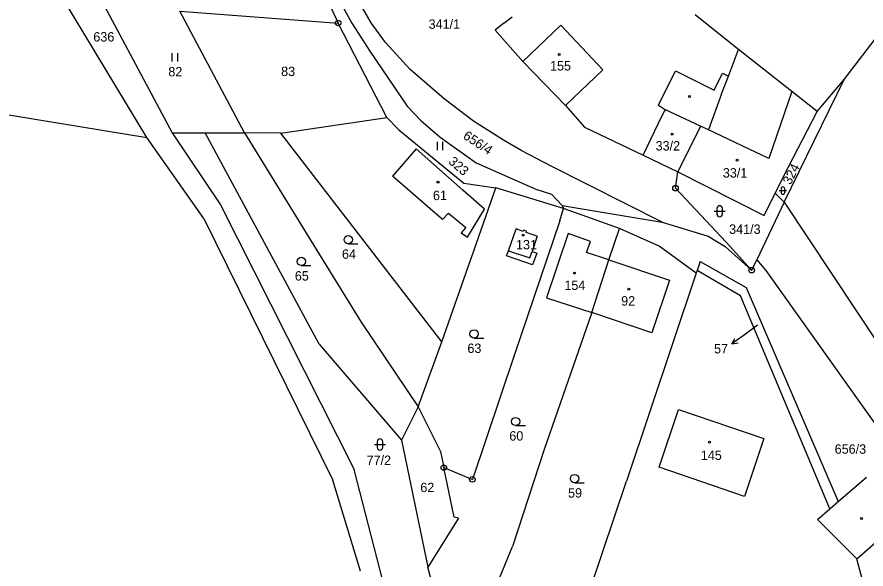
# Model space of a CAD drawing. Extents: x -654459 to -653618, y -1151040 to -1150446.
# Drawn here: x -654178.6 to -654025.1, y -1150786 to -1150686.2 of the extents above; entities that cross this region are included whole.
import ezdxf

# ---------------------------------------------------------------- set-up
doc = ezdxf.new("R2010")
doc.units = 0
for name, color, linetype in [('Vrstva 1', 7, 'Continuous'), ('Vrstva 13', 7, 'Continuous'), ('Vrstva 2', 7, 'Continuous'), ('Vrstva 3', 7, 'Continuous'), ('Vrstva 4', 7, 'Continuous'), ('Vrstva 5', 7, 'Continuous'), ('Vrstva 7', 7, 'Continuous'), ('Vrstva 8', 7, 'Continuous')]:
    doc.layers.add(name, color=color, linetype=linetype)

msp = doc.modelspace()

# ---------------------------------------------------------------- linework, layer by layer
at = {"layer": 'Vrstva 1'}
for points in [[(-654131.26, -1150664.02), (-654120.48, -1150687.29)], [(-654121.84, -1150680.33), (-654118.03, -1150687.34)], [(-654155.05, -1150708), (-654170.17, -1150682.99)], [(-654114.5, -1150687.25), (-654117, -1150682.92)], [(-654162.76, -1150684.14), (-654150.52, -1150707.15)], [(-654149.12, -1150685.15), (-654120.48, -1150687.29)], [(-654137.41, -1150707.13), (-654149.12, -1150685.15)], [(-654090.53, -1150687.32), (-654089.06, -1150686.16)], [(-654048.66, -1150691.65), (-654055.93, -1150685.84)], [(-654111.68, -1150704.37), (-654120.48, -1150687.29)], [(-654118.03, -1150687.34), (-654114.77, -1150692.4)], [(-654111.96, -1150690.82), (-654114.5, -1150687.25)], [(-654090.53, -1150687.32), (-654092.08, -1150688.61)], [(-654087.09, -1150694.22), (-654092.08, -1150688.61)], [(-654080.26, -1150687.68), (-654087.09, -1150694.22)], [(-654072.67, -1150695.73), (-654080.26, -1150687.68)], [(-654028.99, -1150697.51), (-654022.86, -1150689.48)], [(-654107.45, -1150695.69), (-654111.96, -1150690.82)], [(-654048.1, -1150692.09), (-654048.66, -1150691.65)], [(-654114.77, -1150692.4), (-654108.01, -1150702.3)], [(-654049.94, -1150696.9), (-654048.1, -1150692.09)], [(-654038.48, -1150699.66), (-654048.1, -1150692.09)], [(-654079.42, -1150702.23), (-654087.09, -1150694.22)], [(-654231.14, -1150695.5), (-654155.05, -1150708)], [(-654101.34, -1150701.02), (-654107.45, -1150695.69)], [(-654072.67, -1150695.73), (-654079.42, -1150702.23)], [(-654062.57, -1150702.16), (-654059.49, -1150695.95)], [(-654059.49, -1150695.95), (-654052.53, -1150699.42)], [(-654052.53, -1150699.42), (-654051, -1150696.34)], [(-654051, -1150696.34), (-654049.94, -1150696.9)], [(-654051.17, -1150700.09), (-654049.94, -1150696.9)], [(-654039.87, -1150719.69), (-654028.99, -1150697.51)], [(-654033.89, -1150703.26), (-654028.99, -1150697.51)], [(-654051.17, -1150700.09), (-654053.55, -1150706.62)], [(-654033.89, -1150703.26), (-654038.48, -1150699.66)], [(-654108.01, -1150702.3), (-654105.54, -1150704.92)], [(-654096.01, -1150705.02), (-654101.34, -1150701.02)], [(-654079.42, -1150702.23), (-654075.94, -1150706.1)], [(-654062.57, -1150702.16), (-654061.3, -1150702.96)], [(-654062.58, -1150705.42), (-654061.54, -1150703.28)], [(-654061.54, -1150703.28), (-654061.3, -1150702.96)], [(-654039.15, -1150713.42), (-654033.89, -1150703.26)], [(-654130.87, -1150707.18), (-654111.68, -1150704.37)], [(-654111.68, -1150704.37), (-654109.55, -1150706.6)], [(-654105.54, -1150704.92), (-654102.04, -1150707.94)], [(-654090.6, -1150708.48), (-654096.01, -1150705.02)], [(-654065.38, -1150711.17), (-654062.58, -1150705.42)], [(-654109.55, -1150706.6), (-654097.78, -1150716.26)], [(-654075.94, -1150706.1), (-654065.38, -1150711.17)], [(-654054.99, -1150705.94), (-654059.06, -1150714.19)], [(-654053.55, -1150706.62), (-654054.99, -1150705.94)], [(-654144.75, -1150722.63), (-654155.05, -1150708)], [(-654150.52, -1150707.15), (-654144.56, -1150707.14)], [(-654150.52, -1150707.15), (-654141.73, -1150720.19)], [(-654144.56, -1150707.14), (-654137.41, -1150707.13)], [(-654123.92, -1150745.35), (-654144.56, -1150707.14)], [(-654130.87, -1150707.18), (-654137.41, -1150707.13)], [(-654137.41, -1150707.13), (-654124.4, -1150728.31)], [(-654101.77, -1150744.94), (-654130.87, -1150707.18)], [(-654102.04, -1150707.94), (-654095.54, -1150712.57)], [(-654087.28, -1150710.4), (-654090.6, -1150708.48)], [(-654081.99, -1150713.15), (-654087.28, -1150710.4)], [(-654065.38, -1150711.17), (-654059.06, -1150714.19)], [(-654095.54, -1150712.57), (-654084.76, -1150717.3)], [(-654061.89, -1150723.28), (-654081.99, -1150713.15)], [(-654059.5, -1150717.14), (-654059.06, -1150714.19)], [(-654059.06, -1150714.19), (-654043.47, -1150722.09)], [(-654041.46, -1150718.06), (-654039.15, -1150713.42)], [(-654097.78, -1150716.26), (-654091.99, -1150717.11)], [(-654096.4, -1150729.66), (-654091.99, -1150717.11)], [(-654079.78, -1150720.84), (-654091.99, -1150717.11)], [(-654084.76, -1150717.3), (-654081.93, -1150718.26)], [(-654050.37, -1150726.94), (-654059.5, -1150717.14)], [(-654081.93, -1150718.26), (-654080.02, -1150720.28)], [(-654043.47, -1150722.09), (-654041.46, -1150718.06)], [(-654039.87, -1150719.69), (-654041.46, -1150718.06)], [(-654141.73, -1150720.19), (-654117.57, -1150767.99)], [(-654080.44, -1150723.06), (-654079.78, -1150720.84)], [(-654080.02, -1150720.28), (-654061.89, -1150723.28)], [(-654080.02, -1150720.28), (-654079.78, -1150720.84)], [(-654069.62, -1150724.41), (-654079.78, -1150720.84)], [(-654039.87, -1150719.69), (-654044.79, -1150730.11)], [(-654039.87, -1150719.69), (-654022.63, -1150745.66)], [(-654144.75, -1150722.63), (-654121.45, -1150769.94)], [(-654080.44, -1150723.06), (-654088.59, -1150747.23)], [(-654061.89, -1150723.28), (-654053.61, -1150725.85)], [(-654089.72, -1150728.45), (-654088.33, -1150724.53)], [(-654087.03, -1150724.97), (-654088.33, -1150724.53)], [(-654086.95, -1150724.73), (-654087.03, -1150724.97)], [(-654086.43, -1150724.9), (-654086.95, -1150724.73)], [(-654086.51, -1150725.14), (-654086.43, -1150724.9)], [(-654084.51, -1150725.81), (-654086.51, -1150725.14)], [(-654078.93, -1150725.34), (-654082.84, -1150736.98)], [(-654074.89, -1150726.76), (-654078.93, -1150725.34)], [(-654071.54, -1150730.12), (-654069.62, -1150724.41)], [(-654062.45, -1150727.64), (-654069.62, -1150724.41)], [(-654084.51, -1150725.81), (-654085.4, -1150728.6)], [(-654075.58, -1150728.78), (-654074.89, -1150726.76)], [(-654053.61, -1150725.85), (-654050.54, -1150727.71)], [(-654045.74, -1150731.98), (-654050.37, -1150726.94)], [(-654124.4, -1150728.31), (-654116.31, -1150741.38)], [(-654090.03, -1150729.39), (-654089.72, -1150728.45)], [(-654055.78, -1150732.53), (-654062.45, -1150727.64)], [(-654045.74, -1150731.98), (-654050.54, -1150727.71)], [(-654096.99, -1150731.36), (-654096.4, -1150729.66)], [(-654085.33, -1150730.99), (-654090.03, -1150729.39)], [(-654085.4, -1150728.6), (-654084.6, -1150728.9)], [(-654084.6, -1150728.9), (-654085.33, -1150730.99)], [(-654071.54, -1150730.12), (-654075.58, -1150728.78)], [(-654074.64, -1150739.61), (-654071.54, -1150730.12)], [(-654071.54, -1150730.12), (-654060.58, -1150733.8)], [(-654044.79, -1150730.11), (-654045.74, -1150731.98)], [(-654044.79, -1150730.11), (-654043.19, -1150732.01)], [(-654101.77, -1150744.94), (-654096.99, -1150731.36)], [(-654055.06, -1150730.39), (-654055.6, -1150732.01)], [(-654055.06, -1150730.39), (-654046.74, -1150735.11)], [(-654055.78, -1150732.53), (-654068.36, -1150770.11)], [(-654055.6, -1150732.01), (-654055.78, -1150732.53)], [(-654047.78, -1150736.6), (-654055.6, -1150732.01)], [(-654043.19, -1150732.01), (-654008, -1150781.45)], [(-654060.58, -1150733.8), (-654063.76, -1150743.32)], [(-654046.74, -1150735.11), (-654030.11, -1150773.82)], [(-654082.84, -1150736.98), (-654074.64, -1150739.61)], [(-654031.63, -1150775.12), (-654047.78, -1150736.6)], [(-654074.64, -1150739.61), (-654083.25, -1150764.37)], [(-654063.76, -1150743.32), (-654074.64, -1150739.61)], [(-654116.31, -1150741.38), (-654106.01, -1150756.65)], [(-654123.92, -1150745.35), (-654109.03, -1150762.72)], [(-654106.01, -1150756.65), (-654101.77, -1150744.94)], [(-654088.59, -1150747.23), (-654096.22, -1150769.8)], [(-654106.01, -1150756.65), (-654109.03, -1150762.72)], [(-654106.01, -1150756.65), (-654101.99, -1150764.78)], [(-654062.43, -1150767.61), (-654058.99, -1150757.16)], [(-654058.99, -1150757.16), (-654043.51, -1150762.41)], [(-654109.03, -1150762.72), (-654104.28, -1150785.64)], [(-654043.51, -1150762.41), (-654047.01, -1150772.88)], [(-654101.99, -1150764.78), (-654101.39, -1150767.67)], [(-654083.25, -1150764.37), (-654088.98, -1150781.92)], [(-654111.94, -1150790.03), (-654117.57, -1150767.99)], [(-654099.51, -1150776.6), (-654101.39, -1150767.67)], [(-654101.39, -1150767.67), (-654096.22, -1150769.8)], [(-654047.01, -1150772.88), (-654062.43, -1150767.61)], [(-654116.45, -1150786.36), (-654121.45, -1150769.94)], [(-654030.11, -1150773.82), (-654024.99, -1150769.41)], [(-654081.45, -1150808.97), (-654068.36, -1150770.11)], [(-654031.63, -1150775.12), (-654030.11, -1150773.82)], [(-654033.84, -1150777.02), (-654031.63, -1150775.12)], [(-654098.74, -1150776.78), (-654104.28, -1150785.64)], [(-654098.74, -1150776.78), (-654099.51, -1150776.6)], [(-654026.75, -1150784.17), (-654033.84, -1150777.02)], [(-654095.8, -1150798.49), (-654088.98, -1150781.92)], [(-654021.7, -1150802.89), (-654026.75, -1150784.17)], [(-654099.58, -1150803.17), (-654104.28, -1150785.64)]]:
    msp.add_lwpolyline(points, dxfattribs=at)
at = {"layer": 'Vrstva 3'}
for p, q in [((-654150.49, -1150694.24), (-654150.49, -1150692.74)), ((-654149.49, -1150694.24), (-654149.49, -1150692.74)), ((-654102.54, -1150710.28), (-654102.54, -1150708.78)), ((-654101.54, -1150710.28), (-654101.54, -1150708.78)), ((-654040.75, -1150717.58), (-654039.41, -1150717.58)), ((-654040.42, -1150717.25), (-654040.42, -1150717.92)), ((-654039.74, -1150717.92), (-654039.74, -1150717.25)), ((-654052.02, -1150720.83), (-654052.02, -1150721.83)), ((-654051.02, -1150721.83), (-654051.02, -1150720.83)), ((-654052.52, -1150721.33), (-654050.52, -1150721.33)), ((-654118.67, -1150727.21), (-654116.92, -1150727.21)), ((-654127.15, -1150731.15), (-654125.4, -1150731.15)), ((-654095.92, -1150744.24), (-654094.17, -1150744.24)), ((-654088.4, -1150760.08), (-654086.65, -1150760.08)), ((-654113.94, -1150763.49), (-654111.94, -1150763.49)), ((-654113.44, -1150762.99), (-654113.44, -1150763.99)), ((-654112.44, -1150763.99), (-654112.44, -1150762.99)), ((-654077.76, -1150770.39), (-654076.01, -1150770.39))]:
    msp.add_line(p, q, dxfattribs=at)
for centre in [(-654118.67, -1150726.46), (-654127.15, -1150730.4), (-654095.92, -1150743.49), (-654088.4, -1150759.33), (-654077.76, -1150769.64)]:
    msp.add_circle(centre, 0.75, dxfattribs=at)
for centre, radius, start, end in [((-654040.08, -1150717.25), 0.335, 0, 180), ((-654040.08, -1150717.92), 0.335, 180, 359.9879), ((-654051.52, -1150720.83), 0.5, 0, 180), ((-654051.52, -1150721.83), 0.5, 180, 359.9879), ((-654112.94, -1150762.99), 0.5, 0, 180), ((-654112.94, -1150763.99), 0.5, 180, 359.9879)]:
    msp.add_arc(centre, radius, start, end, dxfattribs=at)
at = {"layer": 'Vrstva 4'}
for points in [[(-654038.48, -1150699.66), (-654042.63, -1150711.78)], [(-654054.99, -1150705.94), (-654061.3, -1150702.96)], [(-654042.63, -1150711.78), (-654053.55, -1150706.62)], [(-654106.4, -1150710.03), (-654110.64, -1150714.99)], [(-654097.96, -1150717.51), (-654106.4, -1150710.03)], [(-654101.61, -1150722.8), (-654110.64, -1150714.99)], [(-654094.06, -1150720.92), (-654097.96, -1150717.51)], [(-654097.1, -1150726), (-654094.06, -1150720.92)], [(-654100.57, -1150721.65), (-654101.61, -1150722.8)], [(-654100.57, -1150721.65), (-654097.39, -1150724.24)], [(-654097.39, -1150724.24), (-654098.23, -1150725.22)], [(-654098.23, -1150725.22), (-654097.1, -1150726)], [(-654089.72, -1150728.45), (-654085.82, -1150729.75)], [(-654085.82, -1150729.75), (-654085.4, -1150728.6)], [(-654026.75, -1150784.17), (-654017.92, -1150776.47)]]:
    msp.add_lwpolyline(points, dxfattribs=at)
at = {"layer": 'Vrstva 5'}
for centre in [(-654080.51, -1150692.99), (-654057, -1150700.56), (-654060.11, -1150707.38), (-654048.34, -1150712.08), (-654102.44, -1150716.06), (-654087.07, -1150725.62), (-654077.75, -1150732.49), (-654067.94, -1150735.42), (-654053.38, -1150763.08), (-654025.87, -1150776.88)]:
    msp.add_circle(centre, 0.175, dxfattribs=at)
at = {"layer": 'Vrstva 7'}
for p, q in [((-654046.88, -1150743.55), (-654049.31, -1150745.32)), ((-654049.31, -1150745.32), (-654048.79, -1150744.32)), ((-654049.31, -1150745.32), (-654048.2, -1150745.13))]:
    msp.add_line(p, q, dxfattribs=at)
msp.add_lwpolyline([(-654044.66, -1150741.94), (-654046.88, -1150743.55)], dxfattribs=at)
at = {"layer": 'Vrstva 8'}
for centre, radius in [((-654120.48, -1150687.29), 0.5), ((-654120.48, -1150687.29), 0.0303), ((-654059.5, -1150717.14), 0.5), ((-654059.5, -1150717.14), 0.0303), ((-654045.74, -1150731.98), 0.5), ((-654045.74, -1150731.98), 0.0303), ((-654101.39, -1150767.67), 0.5), ((-654101.39, -1150767.67), 0.0303), ((-654096.22, -1150769.8), 0.5), ((-654096.22, -1150769.8), 0.0303)]:
    msp.add_circle(centre, radius, dxfattribs=at)

# ---------------------------------------------------------------- texts
at = {"layer": 'Vrstva 13'}
for s, p in [('155', (-654082.19, -1150695.88)), ('33/2', (-654063.1, -1150710.34)), ('33/1', (-654050.95, -1150715.23)), ('61', (-654103.35, -1150719.31)), ('131', (-654088.34, -1150728.21)), ('154', (-654079.6, -1150735.55)), ('92', (-654069.33, -1150738.37)), ('145', (-654054.93, -1150766.28))]:
    msp.add_text(s, height=1.7, dxfattribs=at).set_placement(p)
at = {"layer": 'Vrstva 2'}
for s, height, p in [('341/1', 1.7, (-654104.14, -1150688.34)), ('636', 1.7, (-654164.75, -1150690.64)), ('82', 1.7, (-654151.19, -1150696.94)), ('83', 1.7, (-654130.8, -1150696.88)), ('341/3', 1.7, (-654049.81, -1150725.41)), ('64', 1.7, (-654119.8, -1150729.91)), ('65', 1.7, (-654128.32, -1150733.85)), ('57', 0.1, (-654044.73, -1150741.94)), ('63', 1.7, (-654097.12, -1150746.94)), ('60', 1.7, (-654089.55, -1150762.78)), ('656/3', 1.7, (-654030.73, -1150765.16)), ('77/2', 1.7, (-654115.35, -1150767.19)), ('62', 1.7, (-654105.64, -1150772.1)), ('59', 1.7, (-654078.93, -1150773.09))]:
    msp.add_text(s, height=height, dxfattribs=at).set_placement(p)
for s, rotation, p in [('656/4', 326.5417, (-654098.05, -1150708.07)), ('323', 319.4721, (-654100.68, -1150712.55)), ('324', 62.9818, (-654038.71, -1150716.66))]:
    msp.add_text(s, height=1.7, rotation=rotation, dxfattribs=at).set_placement(p)
at = {"layer": 'Vrstva 7'}
msp.add_text('57', height=1.7, dxfattribs=at).set_placement((-654052.54, -1150747.02))

doc.saveas('drawing.dxf')
